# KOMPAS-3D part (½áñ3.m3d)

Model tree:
1. Эскиз:1
2. Операция выдавливания:1
     Расстояние 1 = 20
3. Эскиз:2
4. Операция выдавливания:2
     Расстояние 1 = 400
5. Эскиз:3
6. Вырезать элемент выдавливания:1
     Расстояние 1 = 70
7. Эскиз:4
8. Вырезать элемент выдавливания:2
     Расстояние 1 = 2
9. Эскиз:5
10. Эскиз:6
11. Вырезать элемент выдавливания:3
     Расстояние 2 = 40; Расстояние 1 = 36
12. Эскиз:9
13. Вырезать элемент выдавливания:5
     Расстояние 1 = 40
14. Эскиз:10
15. Вырезать элемент выдавливания:6
     Расстояние 1 = 40
